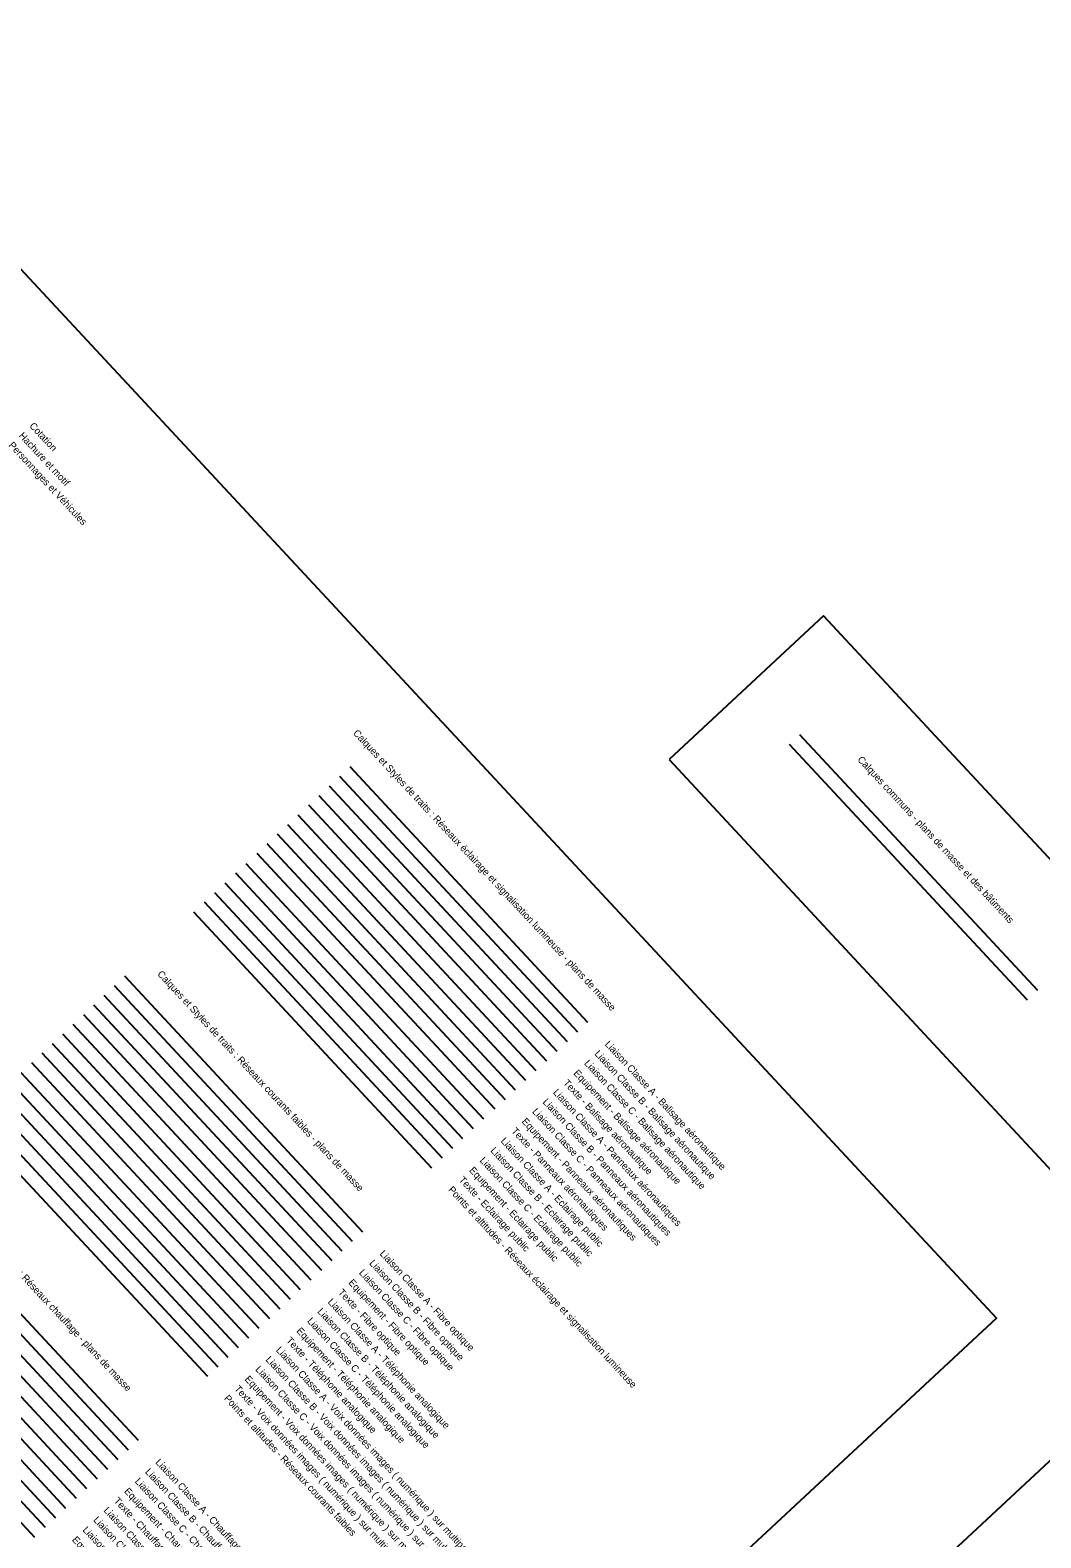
# Model space of a CAD drawing. Extents: x 704383 to 706615, y 7057567 to 7059313.
# Drawn here: x 706498.3 to 706570.1, y 7057704.4 to 7057811.5 of the extents above; entities that cross this region are included whole.
import ezdxf

# ---------------------------------------------------------------- set-up
doc = ezdxf.new("R2010")
doc.units = 0
for name, color, linetype in [('DH_CADRE -CARTOUCHE', 7, 'Continuous'), ('DH_NORD', 7, 'Continuous'), ('MASSE_DH_COTATION', 7, 'Continuous'), ('MASSE_DH_HACHURE-MOTIF', 7, 'Continuous'), ('MASSE_DH_PERSONNAGE_VEHICULES', 7, 'Continuous'), ('R_CF_ALT_POINT', 7, 'Continuous'), ('R_CF_FO_CANALISATION_CL_A', 7, 'Continuous'), ('R_CF_FO_CANALISATION_CL_B', 7, 'Continuous'), ('R_CF_FO_CANALISATION_CL_C', 7, 'Continuous'), ('R_CF_FO_EQUIP', 7, 'Continuous'), ('R_CF_FO_TEXTE', 7, 'Continuous'), ('R_CF_TEL_EQUIP', 7, 'Continuous'), ('R_CF_TEL_LIAISON_CL_A', 7, 'Continuous'), ('R_CF_TEL_LIAISON_CL_B', 7, 'Continuous'), ('R_CF_TEL_LIAISON_CL_C', 7, 'Continuous'), ('R_CF_TEL_TEXTE', 7, 'Continuous'), ('R_CF_VDI_EQUIP', 7, 'Continuous'), ('R_CF_VDI_LIAISON_CL_A', 7, 'Continuous'), ('R_CF_VDI_LIAISON_CL_B', 7, 'Continuous'), ('R_CF_VDI_LIAISON_CL_C', 7, 'Continuous'), ('R_CF_VDI_TEXTE', 7, 'Continuous'), ('R_CH_GEOTHERMIE_CANALISATION_CL_A', 7, 'Continuous'), ('R_CH_PRIM_CANALISATION_CL_A', 7, 'Continuous'), ('R_CH_PRIM_CANALISATION_CL_B', 7, 'Continuous'), ('R_CH_PRIM_CANALISATION_CL_C', 7, 'Continuous'), ('R_CH_PRIM_EQUIP', 7, 'Continuous'), ('R_CH_PRIM_TEXTE', 7, 'Continuous'), ('R_CH_SECOND_CANALISATION_CL_A', 7, 'Continuous'), ('R_CH_SECOND_CANALISATION_CL_B', 7, 'Continuous'), ('R_CH_SECOND_CANALISATION_CL_C', 7, 'Continuous'), ('R_CH_SECOND_EQUIP', 7, 'Continuous'), ('R_CH_SECOND_TEXTE', 7, 'Continuous'), ('R_ECLAIR_AERO_EQUIP', 7, 'Continuous'), ('R_ECLAIR_AERO_LIAISON_CL_A', 7, 'Continuous'), ('R_ECLAIR_AERO_LIAISON_CL_B', 7, 'Continuous'), ('R_ECLAIR_AERO_LIAISON_CL_C', 7, 'Continuous'), ('R_ECLAIR_AERO_TEXTE', 7, 'Continuous'), ('R_ECLAIR_ALT_POINT', 7, 'Continuous'), ('R_ECLAIR_PANNEAU_AERO_EQUIP', 7, 'Continuous'), ('R_ECLAIR_PANNEAU_AERO_LIAISON_CL_A', 7, 'Continuous'), ('R_ECLAIR_PANNEAU_AERO_LIAISON_CL_B', 7, 'Continuous'), ('R_ECLAIR_PANNEAU_AERO_LIAISON_CL_C', 7, 'Continuous'), ('R_ECLAIR_PANNEAU_AERO_TEXTE', 7, 'Continuous'), ('R_ECLAIR_PUB_EQUIP', 7, 'Continuous'), ('R_ECLAIR_PUB_LIAISON_CL_A', 7, 'Continuous'), ('R_ECLAIR_PUB_LIAISON_CL_B', 7, 'Continuous'), ('R_ECLAIR_PUB_LIAISON_CL_C', 7, 'Continuous'), ('R_ECLAIR_PUB_TEXTE', 7, 'Continuous')]:
    doc.layers.add(name, color=color, linetype=linetype)

msp = doc.modelspace()

# ---------------------------------------------------------------- linework, layer by layer
at = {"layer": 'DH_CADRE -CARTOUCHE'}
msp.add_line((706552.97, 7057761.51), (706569.88, 7057743.34), dxfattribs=at)
for points in [[(706481.84, 7057811.55), (706566.98, 7057720.03), (706402.25, 7057566.77), (706317.1, 7057658.29)], [(706543.71, 7057759.72), (706574.36, 7057726.77), (706585.35, 7057736.99), (706554.69, 7057769.94)], [(706573.79, 7057712.71), (706614.66, 7057668.78), (706534.12, 7057593.85), (706493.26, 7057637.78)]]:
    msp.add_lwpolyline(points, close=True, dxfattribs=at)
at = {"layer": 'DH_NORD'}
msp.add_line((706552.24, 7057760.83), (706569.15, 7057742.66), dxfattribs=at)
at = {"layer": 'R_CF_ALT_POINT'}
msp.add_line((706494.01, 7057734.09), (706510.92, 7057715.91), dxfattribs=at)
at = {"layer": 'R_CF_FO_CANALISATION_CL_A'}
msp.add_line((706505.03, 7057744.35), (706521.94, 7057726.18), dxfattribs=at)
at = {"layer": 'R_CF_FO_CANALISATION_CL_B'}
msp.add_line((706504.3, 7057743.67), (706521.21, 7057725.5), dxfattribs=at)
at = {"layer": 'R_CF_FO_CANALISATION_CL_C'}
msp.add_line((706503.57, 7057742.99), (706520.48, 7057724.81), dxfattribs=at)
at = {"layer": 'R_CF_FO_EQUIP'}
msp.add_line((706502.84, 7057742.31), (706519.75, 7057724.13), dxfattribs=at)
at = {"layer": 'R_CF_FO_TEXTE'}
msp.add_line((706502.11, 7057741.62), (706519.02, 7057723.45), dxfattribs=at)
at = {"layer": 'R_CF_TEL_EQUIP'}
msp.add_line((706499.15, 7057738.88), (706516.07, 7057720.7), dxfattribs=at)
at = {"layer": 'R_CF_TEL_LIAISON_CL_A'}
msp.add_line((706501.35, 7057740.92), (706518.26, 7057722.75), dxfattribs=at)
at = {"layer": 'R_CF_TEL_LIAISON_CL_B'}
msp.add_line((706500.62, 7057740.24), (706517.52, 7057722.07), dxfattribs=at)
at = {"layer": 'R_CF_TEL_LIAISON_CL_C'}
msp.add_line((706499.89, 7057739.56), (706516.79, 7057721.39), dxfattribs=at)
at = {"layer": 'R_CF_TEL_TEXTE'}
msp.add_line((706498.42, 7057738.2), (706515.33, 7057720.02), dxfattribs=at)
at = {"layer": 'R_CF_VDI_EQUIP'}
msp.add_line((706495.47, 7057735.45), (706512.38, 7057717.27), dxfattribs=at)
at = {"layer": 'R_CF_VDI_LIAISON_CL_A'}
msp.add_line((706497.67, 7057737.49), (706514.57, 7057719.32), dxfattribs=at)
at = {"layer": 'R_CF_VDI_LIAISON_CL_B'}
msp.add_line((706496.94, 7057736.81), (706513.84, 7057718.64), dxfattribs=at)
at = {"layer": 'R_CF_VDI_LIAISON_CL_C'}
msp.add_line((706496.2, 7057736.13), (706513.11, 7057717.96), dxfattribs=at)
at = {"layer": 'R_CF_VDI_TEXTE'}
msp.add_line((706494.74, 7057734.77), (706511.65, 7057716.59), dxfattribs=at)
at = {"layer": 'R_CH_GEOTHERMIE_CANALISATION_CL_A'}
msp.add_line((706481.72, 7057722.66), (706498.63, 7057704.49), dxfattribs=at)
at = {"layer": 'R_CH_PRIM_CANALISATION_CL_A'}
msp.add_line((706489.11, 7057729.53), (706506.01, 7057711.36), dxfattribs=at)
at = {"layer": 'R_CH_PRIM_CANALISATION_CL_B'}
msp.add_line((706488.38, 7057728.85), (706505.28, 7057710.68), dxfattribs=at)
at = {"layer": 'R_CH_PRIM_CANALISATION_CL_C'}
msp.add_line((706487.64, 7057728.17), (706504.55, 7057710), dxfattribs=at)
at = {"layer": 'R_CH_PRIM_EQUIP'}
msp.add_line((706486.91, 7057727.49), (706503.82, 7057709.31), dxfattribs=at)
at = {"layer": 'R_CH_PRIM_TEXTE'}
msp.add_line((706486.18, 7057726.81), (706503.09, 7057708.63), dxfattribs=at)
at = {"layer": 'R_CH_SECOND_CANALISATION_CL_A'}
msp.add_line((706485.43, 7057726.11), (706502.33, 7057707.93), dxfattribs=at)
at = {"layer": 'R_CH_SECOND_CANALISATION_CL_B'}
msp.add_line((706484.69, 7057725.42), (706501.6, 7057707.25), dxfattribs=at)
at = {"layer": 'R_CH_SECOND_CANALISATION_CL_C'}
msp.add_line((706483.94, 7057724.72), (706500.84, 7057706.55), dxfattribs=at)
at = {"layer": 'R_CH_SECOND_EQUIP'}
msp.add_line((706483.21, 7057724.04), (706500.12, 7057705.86), dxfattribs=at)
at = {"layer": 'R_CH_SECOND_TEXTE'}
msp.add_line((706482.47, 7057723.36), (706499.39, 7057705.18), dxfattribs=at)
at = {"layer": 'R_ECLAIR_AERO_EQUIP'}
msp.add_line((706518.83, 7057757.18), (706535.74, 7057739.01), dxfattribs=at)
at = {"layer": 'R_ECLAIR_AERO_LIAISON_CL_A'}
msp.add_line((706521.03, 7057759.23), (706537.93, 7057741.06), dxfattribs=at)
at = {"layer": 'R_ECLAIR_AERO_LIAISON_CL_B'}
msp.add_line((706520.3, 7057758.55), (706537.2, 7057740.37), dxfattribs=at)
at = {"layer": 'R_ECLAIR_AERO_LIAISON_CL_C'}
msp.add_line((706519.56, 7057757.87), (706536.47, 7057739.69), dxfattribs=at)
at = {"layer": 'R_ECLAIR_AERO_TEXTE'}
msp.add_line((706518.1, 7057756.5), (706535.01, 7057738.32), dxfattribs=at)
at = {"layer": 'R_ECLAIR_ALT_POINT'}
msp.add_line((706509.93, 7057748.91), (706526.84, 7057730.73), dxfattribs=at)
at = {"layer": 'R_ECLAIR_PANNEAU_AERO_EQUIP'}
msp.add_line((706515.15, 7057753.76), (706532.06, 7057735.58), dxfattribs=at)
at = {"layer": 'R_ECLAIR_PANNEAU_AERO_LIAISON_CL_A'}
msp.add_line((706517.34, 7057755.8), (706534.25, 7057737.63), dxfattribs=at)
at = {"layer": 'R_ECLAIR_PANNEAU_AERO_LIAISON_CL_B'}
msp.add_line((706516.61, 7057755.12), (706533.52, 7057736.95), dxfattribs=at)
at = {"layer": 'R_ECLAIR_PANNEAU_AERO_LIAISON_CL_C'}
msp.add_line((706515.88, 7057754.44), (706532.79, 7057736.27), dxfattribs=at)
at = {"layer": 'R_ECLAIR_PANNEAU_AERO_TEXTE'}
msp.add_line((706514.42, 7057753.08), (706531.33, 7057734.9), dxfattribs=at)
at = {"layer": 'R_ECLAIR_PUB_EQUIP'}
msp.add_line((706511.42, 7057750.29), (706528.33, 7057732.11), dxfattribs=at)
at = {"layer": 'R_ECLAIR_PUB_LIAISON_CL_A'}
msp.add_line((706513.64, 7057752.35), (706530.53, 7057734.2), dxfattribs=at)
at = {"layer": 'R_ECLAIR_PUB_LIAISON_CL_B'}
msp.add_line((706512.91, 7057751.67), (706529.8, 7057733.51), dxfattribs=at)
at = {"layer": 'R_ECLAIR_PUB_LIAISON_CL_C'}
msp.add_line((706512.15, 7057750.97), (706529.04, 7057732.81), dxfattribs=at)
at = {"layer": 'R_ECLAIR_PUB_TEXTE'}
msp.add_line((706510.69, 7057749.61), (706527.6, 7057731.43), dxfattribs=at)

# ---------------------------------------------------------------- texts
at = {"layer": 'DH_CADRE -CARTOUCHE'}
for s, p in [(' Calques et Styles de traits : Réseaux éclairage et signalisation lumineuse - plans de masse', (706521.11, 7057761.71)), ('Calques communs - plans de masse et des bâtiments', (706557.06, 7057759.69)), (' Calques et Styles de traits : Réseaux courants faibles - plans de masse', (706507.2, 7057744.59)), (' Calques et Styles de traits : Réseaux chauffage - plans de masse', (706491.9, 7057729.1))]:
    msp.add_text(s, height=0.5, rotation=312.9332, dxfattribs=at).set_placement(p)
at = {"layer": 'MASSE_DH_COTATION'}
msp.add_text('Cotation', height=0.5, rotation=312.9332, dxfattribs=at).set_placement((706498.24, 7057783.4))
at = {"layer": 'MASSE_DH_HACHURE-MOTIF'}
msp.add_text('Hachure et motif', height=0.5, rotation=312.9332, dxfattribs=at).set_placement((706497.49, 7057782.7))
at = {"layer": 'MASSE_DH_PERSONNAGE_VEHICULES'}
msp.add_text('Personnages et Véhicules', height=0.5, rotation=312.9332, dxfattribs=at).set_placement((706496.76, 7057782.02))
at = {"layer": 'R_CF_ALT_POINT'}
msp.add_text('Points et altitudes - Réseaux courants faibles', height=0.5, rotation=312.9332, dxfattribs=at).set_placement((706512.07, 7057714.31))
at = {"layer": 'R_CF_FO_CANALISATION_CL_A'}
msp.add_text('Liaison Classe A - Fibre optique', height=0.5, rotation=312.9332, dxfattribs=at).set_placement((706523.12, 7057724.59))
at = {"layer": 'R_CF_FO_CANALISATION_CL_B'}
msp.add_text('Liaison Classe B - Fibre optique', height=0.5, rotation=312.9332, dxfattribs=at).set_placement((706522.38, 7057723.91))
at = {"layer": 'R_CF_FO_CANALISATION_CL_C'}
msp.add_text('Liaison Classe C - Fibre optique', height=0.5, rotation=312.9332, dxfattribs=at).set_placement((706521.65, 7057723.23))
at = {"layer": 'R_CF_FO_EQUIP'}
msp.add_text('Equipement - Fibre optique', height=0.5, rotation=312.9332, dxfattribs=at).set_placement((706520.9, 7057722.53))
at = {"layer": 'R_CF_FO_TEXTE'}
msp.add_text('Texte - Fibre optique', height=0.5, rotation=312.9332, dxfattribs=at).set_placement((706520.17, 7057721.84))
at = {"layer": 'R_CF_TEL_EQUIP'}
msp.add_text('Equipement - Téléphonie analogique', height=0.5, rotation=312.9332, dxfattribs=at).set_placement((706517.21, 7057719.1))
at = {"layer": 'R_CF_TEL_LIAISON_CL_A'}
msp.add_text('Liaison Classe A - Téléphonie analogique', height=0.5, rotation=312.9332, dxfattribs=at).set_placement((706519.43, 7057721.16))
at = {"layer": 'R_CF_TEL_LIAISON_CL_B'}
msp.add_text('Liaison Classe B - Téléphonie analogique', height=0.5, rotation=312.9332, dxfattribs=at).set_placement((706518.7, 7057720.48))
at = {"layer": 'R_CF_TEL_LIAISON_CL_C'}
msp.add_text('Liaison Classe C - Téléphonie analogique', height=0.5, rotation=312.9332, dxfattribs=at).set_placement((706517.97, 7057719.8))
at = {"layer": 'R_CF_TEL_TEXTE'}
msp.add_text('Texte - Téléphonie analogique', height=0.5, rotation=312.9332, dxfattribs=at).set_placement((706516.48, 7057718.42))
at = {"layer": 'R_CF_VDI_EQUIP'}
msp.add_text('Equipement - Voix données images ( numérique ) sur multipaires cuivre et coaxial', height=0.5, rotation=312.9332, dxfattribs=at).set_placement((706513.53, 7057715.67))
at = {"layer": 'R_CF_VDI_LIAISON_CL_A'}
msp.add_text('Liaison Classe A - Voix données images ( numérique ) sur multipaires cuivre et coaxial', height=0.5, rotation=312.9332, dxfattribs=at).set_placement((706515.75, 7057717.74))
at = {"layer": 'R_CF_VDI_LIAISON_CL_B'}
msp.add_text('Liaison Classe B - Voix données images ( numérique ) sur multipaires cuivre et coaxial', height=0.5, rotation=312.9332, dxfattribs=at).set_placement((706515.02, 7057717.06))
at = {"layer": 'R_CF_VDI_LIAISON_CL_C'}
msp.add_text('Liaison Classe C - Voix données images ( numérique ) sur multipaires cuivre et coaxial', height=0.5, rotation=312.9332, dxfattribs=at).set_placement((706514.29, 7057716.37))
at = {"layer": 'R_CF_VDI_TEXTE'}
msp.add_text('Texte - Voix données images ( numérique ) sur multipaires cuivre et coaxial', height=0.5, rotation=312.9332, dxfattribs=at).set_placement((706512.8, 7057714.99))
at = {"layer": 'R_CH_PRIM_CANALISATION_CL_A'}
msp.add_text('Liaison Classe A - Chauffage - primaire', height=0.5, rotation=312.9332, dxfattribs=at).set_placement((706507.19, 7057709.77))
at = {"layer": 'R_CH_PRIM_CANALISATION_CL_B'}
msp.add_text('Liaison Classe B - Chauffage - primaire', height=0.5, rotation=312.9332, dxfattribs=at).set_placement((706506.46, 7057709.09))
at = {"layer": 'R_CH_PRIM_CANALISATION_CL_C'}
msp.add_text('Liaison Classe C - Chauffage - primaire', height=0.5, rotation=312.9332, dxfattribs=at).set_placement((706505.73, 7057708.41))
at = {"layer": 'R_CH_PRIM_EQUIP'}
msp.add_text('Equipement - Chauffage - primaire', height=0.5, rotation=312.9332, dxfattribs=at).set_placement((706504.97, 7057707.71))
at = {"layer": 'R_CH_PRIM_TEXTE'}
msp.add_text('Texte - Chauffage - primaire', height=0.5, rotation=312.9332, dxfattribs=at).set_placement((706504.24, 7057707.03))
at = {"layer": 'R_CH_SECOND_CANALISATION_CL_A'}
msp.add_text('Liaison Classe A - Chauffage - secondaire ', height=0.5, rotation=312.9332, dxfattribs=at).set_placement((706503.51, 7057706.35))
at = {"layer": 'R_CH_SECOND_CANALISATION_CL_B'}
msp.add_text('Liaison Classe B - Chauffage - secondaire ', height=0.5, rotation=312.9332, dxfattribs=at).set_placement((706502.78, 7057705.67))
at = {"layer": 'R_CH_SECOND_CANALISATION_CL_C'}
msp.add_text('Liaison Classe C - Chauffage - secondaire ', height=0.5, rotation=312.9332, dxfattribs=at).set_placement((706502.02, 7057704.96))
at = {"layer": 'R_CH_SECOND_EQUIP'}
msp.add_text('Equipement - Chauffage - secondaire ', height=0.5, rotation=312.9332, dxfattribs=at).set_placement((706501.27, 7057704.26))
at = {"layer": 'R_ECLAIR_AERO_EQUIP'}
msp.add_text('Equipement - Balisage aéronautique', height=0.5, rotation=312.9332, dxfattribs=at).set_placement((706536.89, 7057737.41))
at = {"layer": 'R_ECLAIR_AERO_LIAISON_CL_A'}
msp.add_text('Liaison Classe A - Balisage aéronautique', height=0.5, rotation=312.9332, dxfattribs=at).set_placement((706539.11, 7057739.47))
at = {"layer": 'R_ECLAIR_AERO_LIAISON_CL_B'}
msp.add_text('Liaison Classe B - Balisage aéronautique', height=0.5, rotation=312.9332, dxfattribs=at).set_placement((706538.38, 7057738.79))
at = {"layer": 'R_ECLAIR_AERO_LIAISON_CL_C'}
msp.add_text('Liaison Classe C - Balisage aéronautique', height=0.5, rotation=312.9332, dxfattribs=at).set_placement((706537.65, 7057738.11))
at = {"layer": 'R_ECLAIR_AERO_TEXTE'}
msp.add_text('Texte - Balisage aéronautique', height=0.5, rotation=312.9332, dxfattribs=at).set_placement((706536.16, 7057736.72))
at = {"layer": 'R_ECLAIR_ALT_POINT'}
msp.add_text('Points et altitudes - Réseaux éclairage et signalisation lumineuse', height=0.5, rotation=312.9332, dxfattribs=at).set_placement((706527.99, 7057729.13))
at = {"layer": 'R_ECLAIR_PANNEAU_AERO_EQUIP'}
msp.add_text('Equipement - Panneaux aéronautiques', height=0.5, rotation=312.9332, dxfattribs=at).set_placement((706533.21, 7057733.98))
at = {"layer": 'R_ECLAIR_PANNEAU_AERO_LIAISON_CL_A'}
msp.add_text('Liaison Classe A - Panneaux aéronautiques', height=0.5, rotation=312.9332, dxfattribs=at).set_placement((706535.43, 7057736.04))
at = {"layer": 'R_ECLAIR_PANNEAU_AERO_LIAISON_CL_B'}
msp.add_text('Liaison Classe B - Panneaux aéronautiques', height=0.5, rotation=312.9332, dxfattribs=at).set_placement((706534.7, 7057735.36))
at = {"layer": 'R_ECLAIR_PANNEAU_AERO_LIAISON_CL_C'}
msp.add_text('Liaison Classe C - Panneaux aéronautiques', height=0.5, rotation=312.9332, dxfattribs=at).set_placement((706533.96, 7057734.68))
at = {"layer": 'R_ECLAIR_PANNEAU_AERO_TEXTE'}
msp.add_text('Texte - Panneaux aéronautiques', height=0.5, rotation=312.9332, dxfattribs=at).set_placement((706532.48, 7057733.3))
at = {"layer": 'R_ECLAIR_PUB_EQUIP'}
msp.add_text('Equipement - Eclairage public', height=0.5, rotation=312.9332, dxfattribs=at).set_placement((706529.48, 7057730.51))
at = {"layer": 'R_ECLAIR_PUB_LIAISON_CL_A'}
msp.add_text('Liaison Classe A - Eclairage public', height=0.5, rotation=312.9332, dxfattribs=at).set_placement((706531.72, 7057732.6))
at = {"layer": 'R_ECLAIR_PUB_LIAISON_CL_B'}
msp.add_text('Liaison Classe B - Eclairage public', height=0.5, rotation=312.9332, dxfattribs=at).set_placement((706530.99, 7057731.91))
at = {"layer": 'R_ECLAIR_PUB_LIAISON_CL_C'}
msp.add_text('Liaison Classe C - Eclairage public', height=0.5, rotation=312.9332, dxfattribs=at).set_placement((706530.23, 7057731.21))
at = {"layer": 'R_ECLAIR_PUB_TEXTE'}
msp.add_text('Texte - Eclairage public', height=0.5, rotation=312.9332, dxfattribs=at).set_placement((706528.75, 7057729.83))

doc.saveas('drawing.dxf')
